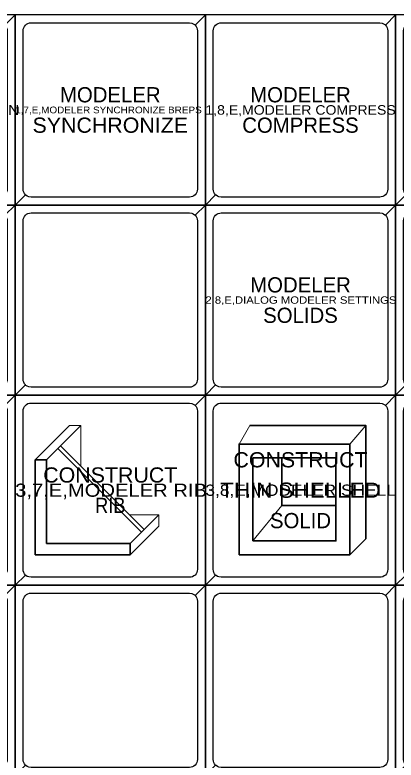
# Model space of a CAD drawing. Extents: x 95909.2 to 95923.3, y 90965 to 90971.2.
# Drawn here: x 95913.386 to 95914.588, y 90968.808 to 90971.16 of the extents above; entities that cross this region are included whole.
import ezdxf
from ezdxf.enums import TextEntityAlignment as Align

# ---------------------------------------------------------------- set-up
doc = ezdxf.new("R2010")
doc.units = 0
doc.header["$LTSCALE"] = 0.019
for name, color, linetype, lineweight in [('1', 7, 'Continuous', 25), ('10', 7, 'Continuous', 13), ('2', 7, 'Continuous', 25), ('3', 7, 'Continuous', 25), ('4', 7, 'Continuous', 25), ('6', 7, 'Continuous', 13)]:
    doc.layers.add(name, color=color, linetype=linetype, lineweight=lineweight)
for name, color, linetype in [('5', 7, 'Continuous'), ('63', 7, 'Continuous'), ('9', 7, 'Continuous')]:
    doc.layers.add(name, color=color, linetype=linetype)

msp = doc.modelspace()

# ---------------------------------------------------------------- linework, layer by layer
at = {"layer": '1'}
for points in [[(95912.7868, 90970.5603), (95913.3868, 90970.5603), (95913.3868, 90971.1603), (95912.7868, 90971.1603)], [(95913.3868, 90970.5603), (95913.9868, 90970.5603), (95913.9868, 90971.1603), (95913.3868, 90971.1603)], [(95913.9868, 90970.5603), (95914.5868, 90970.5603), (95914.5868, 90971.1603), (95913.9868, 90971.1603)], [(95914.5868, 90970.5603), (95915.1868, 90970.5603), (95915.1868, 90971.1603), (95914.5868, 90971.1603)], [(95912.7868, 90969.9603), (95913.3868, 90969.9603), (95913.3868, 90970.5603), (95912.7868, 90970.5603)], [(95913.3868, 90969.9603), (95913.9868, 90969.9603), (95913.9868, 90970.5603), (95913.3868, 90970.5603)], [(95913.9868, 90969.9603), (95914.5868, 90969.9603), (95914.5868, 90970.5603), (95913.9868, 90970.5603)], [(95914.5868, 90969.9603), (95915.1868, 90969.9603), (95915.1868, 90970.5603), (95914.5868, 90970.5603)], [(95912.7868, 90969.3603), (95913.3868, 90969.3603), (95913.3868, 90969.9603), (95912.7868, 90969.9603)], [(95913.3868, 90969.3603), (95913.9868, 90969.3603), (95913.9868, 90969.9603), (95913.3868, 90969.9603)], [(95913.9868, 90969.3603), (95914.5868, 90969.3603), (95914.5868, 90969.9603), (95913.9868, 90969.9603)], [(95914.5868, 90969.3603), (95915.1868, 90969.3603), (95915.1868, 90969.9603), (95914.5868, 90969.9603)], [(95912.7868, 90968.7603), (95913.3868, 90968.7603), (95913.3868, 90969.3603), (95912.7868, 90969.3603)], [(95913.3868, 90968.7603), (95913.9868, 90968.7603), (95913.9868, 90969.3603), (95913.3868, 90969.3603)], [(95913.9868, 90968.7603), (95914.5868, 90968.7603), (95914.5868, 90969.3603), (95913.9868, 90969.3603)], [(95914.5868, 90968.7603), (95915.1868, 90968.7603), (95915.1868, 90969.3603), (95914.5868, 90969.3603)]]:
    msp.add_lwpolyline(points, close=True, dxfattribs=at)
at = {"layer": '10'}
msp.add_lwpolyline([(95909.7868, 90971.1603), (95915.7868, 90971.1603), (95915.7868, 90966.3603), (95909.7868, 90966.3603)], close=True, dxfattribs=at)
at = {"layer": '2'}
for points in [[(95912.7868, 90970.5603), (95913.3868, 90970.5603), (95913.3868, 90971.1603), (95912.7868, 90971.1603)], [(95913.3868, 90970.5603), (95913.9868, 90970.5603), (95913.9868, 90971.1603), (95913.3868, 90971.1603)], [(95913.9868, 90970.5603), (95914.5868, 90970.5603), (95914.5868, 90971.1603), (95913.9868, 90971.1603)], [(95914.5868, 90970.5603), (95915.1868, 90970.5603), (95915.1868, 90971.1603), (95914.5868, 90971.1603)], [(95912.7868, 90969.9603), (95913.3868, 90969.9603), (95913.3868, 90970.5603), (95912.7868, 90970.5603)], [(95913.3868, 90969.9603), (95913.9868, 90969.9603), (95913.9868, 90970.5603), (95913.3868, 90970.5603)], [(95913.9868, 90969.9603), (95914.5868, 90969.9603), (95914.5868, 90970.5603), (95913.9868, 90970.5603)], [(95914.5868, 90969.9603), (95915.1868, 90969.9603), (95915.1868, 90970.5603), (95914.5868, 90970.5603)], [(95912.7868, 90969.3603), (95913.3868, 90969.3603), (95913.3868, 90969.9603), (95912.7868, 90969.9603)], [(95913.3868, 90969.3603), (95913.9868, 90969.3603), (95913.9868, 90969.9603), (95913.3868, 90969.9603)], [(95913.9868, 90969.3603), (95914.5868, 90969.3603), (95914.5868, 90969.9603), (95913.9868, 90969.9603)], [(95914.5868, 90969.3603), (95915.1868, 90969.3603), (95915.1868, 90969.9603), (95914.5868, 90969.9603)], [(95912.7868, 90968.7603), (95913.3868, 90968.7603), (95913.3868, 90969.3603), (95912.7868, 90969.3603)], [(95913.3868, 90968.7603), (95913.9868, 90968.7603), (95913.9868, 90969.3603), (95913.3868, 90969.3603)], [(95913.9868, 90968.7603), (95914.5868, 90968.7603), (95914.5868, 90969.3603), (95913.9868, 90969.3603)], [(95914.5868, 90968.7603), (95915.1868, 90968.7603), (95915.1868, 90969.3603), (95914.5868, 90969.3603)]]:
    msp.add_lwpolyline(points, close=True, dxfattribs=at)
at = {"layer": '3'}
for points in [[(95913.3868, 90971.1603), (95912.7868, 90971.1603), (95912.7868, 90970.5603), (95912.8191, 90970.5926), (95912.816, 90970.5964), (95912.8137, 90970.6007), (95912.8123, 90970.6054), (95912.8118, 90970.6103), (95912.8118, 90971.1103), (95912.8123, 90971.1152), (95912.8137, 90971.1199), (95912.816, 90971.1242), (95912.8191, 90971.128), (95912.8191, 90971.128), (95912.8229, 90971.1311), (95912.8272, 90971.1334), (95912.8319, 90971.1348), (95912.8368, 90971.1353), (95913.3368, 90971.1353), (95913.3441, 90971.1342), (95913.3486, 90971.1323), (95913.3527, 90971.1296), (95913.3545, 90971.128)], [(95913.9868, 90971.1603), (95913.3868, 90971.1603), (95913.3868, 90970.5603), (95913.4191, 90970.5926), (95913.416, 90970.5964), (95913.4137, 90970.6007), (95913.4123, 90970.6054), (95913.4118, 90970.6103), (95913.4118, 90971.1103), (95913.4123, 90971.1152), (95913.4137, 90971.1199), (95913.416, 90971.1242), (95913.4191, 90971.128), (95913.4191, 90971.128), (95913.4229, 90971.1311), (95913.4272, 90971.1334), (95913.4319, 90971.1348), (95913.4368, 90971.1353), (95913.9368, 90971.1353), (95913.9441, 90971.1342), (95913.9486, 90971.1323), (95913.9527, 90971.1296), (95913.9545, 90971.128)], [(95914.5868, 90971.1603), (95913.9868, 90971.1603), (95913.9868, 90970.5603), (95914.0191, 90970.5926), (95914.016, 90970.5964), (95914.0137, 90970.6007), (95914.0123, 90970.6054), (95914.0118, 90970.6103), (95914.0118, 90971.1103), (95914.0123, 90971.1152), (95914.0137, 90971.1199), (95914.016, 90971.1242), (95914.0191, 90971.128), (95914.0191, 90971.128), (95914.0229, 90971.1311), (95914.0272, 90971.1334), (95914.0319, 90971.1348), (95914.0368, 90971.1353), (95914.5368, 90971.1353), (95914.5441, 90971.1342), (95914.5486, 90971.1323), (95914.5527, 90971.1296), (95914.5545, 90971.128)], [(95915.1868, 90971.1603), (95914.5868, 90971.1603), (95914.5868, 90970.5603), (95914.6191, 90970.5926), (95914.616, 90970.5964), (95914.6137, 90970.6007), (95914.6123, 90970.6054), (95914.6118, 90970.6103), (95914.6118, 90971.1103), (95914.6123, 90971.1152), (95914.6137, 90971.1199), (95914.616, 90971.1242), (95914.6191, 90971.128), (95914.6191, 90971.128), (95914.6229, 90971.1311), (95914.6272, 90971.1334), (95914.6319, 90971.1348), (95914.6368, 90971.1353), (95915.1368, 90971.1353), (95915.1441, 90971.1342), (95915.1486, 90971.1323), (95915.1527, 90971.1296), (95915.1545, 90971.128)], [(95913.3868, 90970.5603), (95912.7868, 90970.5603), (95912.7868, 90969.9603), (95912.8191, 90969.9926), (95912.816, 90969.9964), (95912.8137, 90970.0007), (95912.8123, 90970.0054), (95912.8118, 90970.0103), (95912.8118, 90970.5103), (95912.8123, 90970.5152), (95912.8137, 90970.5199), (95912.816, 90970.5242), (95912.8191, 90970.528), (95912.8191, 90970.528), (95912.8229, 90970.5311), (95912.8272, 90970.5334), (95912.8319, 90970.5348), (95912.8368, 90970.5353), (95913.3368, 90970.5353), (95913.3441, 90970.5342), (95913.3486, 90970.5323), (95913.3527, 90970.5296), (95913.3545, 90970.528)], [(95913.9868, 90970.5603), (95913.3868, 90970.5603), (95913.3868, 90969.9603), (95913.4191, 90969.9926), (95913.416, 90969.9964), (95913.4137, 90970.0007), (95913.4123, 90970.0054), (95913.4118, 90970.0103), (95913.4118, 90970.5103), (95913.4123, 90970.5152), (95913.4137, 90970.5199), (95913.416, 90970.5242), (95913.4191, 90970.528), (95913.4191, 90970.528), (95913.4229, 90970.5311), (95913.4272, 90970.5334), (95913.4319, 90970.5348), (95913.4368, 90970.5353), (95913.9368, 90970.5353), (95913.9441, 90970.5342), (95913.9486, 90970.5323), (95913.9527, 90970.5296), (95913.9545, 90970.528)], [(95914.5868, 90970.5603), (95913.9868, 90970.5603), (95913.9868, 90969.9603), (95914.0191, 90969.9926), (95914.016, 90969.9964), (95914.0137, 90970.0007), (95914.0123, 90970.0054), (95914.0118, 90970.0103), (95914.0118, 90970.5103), (95914.0123, 90970.5152), (95914.0137, 90970.5199), (95914.016, 90970.5242), (95914.0191, 90970.528), (95914.0191, 90970.528), (95914.0229, 90970.5311), (95914.0272, 90970.5334), (95914.0319, 90970.5348), (95914.0368, 90970.5353), (95914.5368, 90970.5353), (95914.5441, 90970.5342), (95914.5486, 90970.5323), (95914.5527, 90970.5296), (95914.5545, 90970.528)], [(95915.1868, 90970.5603), (95914.5868, 90970.5603), (95914.5868, 90969.9603), (95914.6191, 90969.9926), (95914.616, 90969.9964), (95914.6137, 90970.0007), (95914.6123, 90970.0054), (95914.6118, 90970.0103), (95914.6118, 90970.5103), (95914.6123, 90970.5152), (95914.6137, 90970.5199), (95914.616, 90970.5242), (95914.6191, 90970.528), (95914.6191, 90970.528), (95914.6229, 90970.5311), (95914.6272, 90970.5334), (95914.6319, 90970.5348), (95914.6368, 90970.5353), (95915.1368, 90970.5353), (95915.1441, 90970.5342), (95915.1486, 90970.5323), (95915.1527, 90970.5296), (95915.1545, 90970.528)], [(95913.3868, 90969.9603), (95912.7868, 90969.9603), (95912.7868, 90969.3603), (95912.8191, 90969.3926), (95912.816, 90969.3964), (95912.8137, 90969.4007), (95912.8123, 90969.4054), (95912.8118, 90969.4103), (95912.8118, 90969.9103), (95912.8123, 90969.9152), (95912.8137, 90969.9199), (95912.816, 90969.9242), (95912.8191, 90969.928), (95912.8191, 90969.928), (95912.8229, 90969.9311), (95912.8272, 90969.9334), (95912.8319, 90969.9348), (95912.8368, 90969.9353), (95913.3368, 90969.9353), (95913.3441, 90969.9342), (95913.3486, 90969.9323), (95913.3527, 90969.9296), (95913.3545, 90969.928)], [(95913.9868, 90969.9603), (95913.3868, 90969.9603), (95913.3868, 90969.3603), (95913.4191, 90969.3926), (95913.416, 90969.3964), (95913.4137, 90969.4007), (95913.4123, 90969.4054), (95913.4118, 90969.4103), (95913.4118, 90969.9103), (95913.4123, 90969.9152), (95913.4137, 90969.9199), (95913.416, 90969.9242), (95913.4191, 90969.928), (95913.4191, 90969.928), (95913.4229, 90969.9311), (95913.4272, 90969.9334), (95913.4319, 90969.9348), (95913.4368, 90969.9353), (95913.9368, 90969.9353), (95913.9441, 90969.9342), (95913.9486, 90969.9323), (95913.9527, 90969.9296), (95913.9545, 90969.928)], [(95914.5868, 90969.9603), (95913.9868, 90969.9603), (95913.9868, 90969.3603), (95914.0191, 90969.3926), (95914.016, 90969.3964), (95914.0137, 90969.4007), (95914.0123, 90969.4054), (95914.0118, 90969.4103), (95914.0118, 90969.9103), (95914.0123, 90969.9152), (95914.0137, 90969.9199), (95914.016, 90969.9242), (95914.0191, 90969.928), (95914.0191, 90969.928), (95914.0229, 90969.9311), (95914.0272, 90969.9334), (95914.0319, 90969.9348), (95914.0368, 90969.9353), (95914.5368, 90969.9353), (95914.5441, 90969.9342), (95914.5486, 90969.9323), (95914.5527, 90969.9296), (95914.5545, 90969.928)], [(95915.1868, 90969.9603), (95914.5868, 90969.9603), (95914.5868, 90969.3603), (95914.6191, 90969.3926), (95914.616, 90969.3964), (95914.6137, 90969.4007), (95914.6123, 90969.4054), (95914.6118, 90969.4103), (95914.6118, 90969.9103), (95914.6123, 90969.9152), (95914.6137, 90969.9199), (95914.616, 90969.9242), (95914.6191, 90969.928), (95914.6191, 90969.928), (95914.6229, 90969.9311), (95914.6272, 90969.9334), (95914.6319, 90969.9348), (95914.6368, 90969.9353), (95915.1368, 90969.9353), (95915.1441, 90969.9342), (95915.1486, 90969.9323), (95915.1527, 90969.9296), (95915.1545, 90969.928)], [(95913.3868, 90969.3603), (95912.7868, 90969.3603), (95912.7868, 90968.7603), (95912.8191, 90968.7926), (95912.816, 90968.7964), (95912.8137, 90968.8007), (95912.8123, 90968.8054), (95912.8118, 90968.8103), (95912.8118, 90969.3103), (95912.8123, 90969.3152), (95912.8137, 90969.3199), (95912.816, 90969.3242), (95912.8191, 90969.328), (95912.8191, 90969.328), (95912.8229, 90969.3311), (95912.8272, 90969.3334), (95912.8319, 90969.3348), (95912.8368, 90969.3353), (95913.3368, 90969.3353), (95913.3441, 90969.3342), (95913.3486, 90969.3323), (95913.3527, 90969.3296), (95913.3545, 90969.328)], [(95913.9868, 90969.3603), (95913.3868, 90969.3603), (95913.3868, 90968.7603), (95913.4191, 90968.7926), (95913.416, 90968.7964), (95913.4137, 90968.8007), (95913.4123, 90968.8054), (95913.4118, 90968.8103), (95913.4118, 90969.3103), (95913.4123, 90969.3152), (95913.4137, 90969.3199), (95913.416, 90969.3242), (95913.4191, 90969.328), (95913.4191, 90969.328), (95913.4229, 90969.3311), (95913.4272, 90969.3334), (95913.4319, 90969.3348), (95913.4368, 90969.3353), (95913.9368, 90969.3353), (95913.9441, 90969.3342), (95913.9486, 90969.3323), (95913.9527, 90969.3296), (95913.9545, 90969.328)], [(95914.5868, 90969.3603), (95913.9868, 90969.3603), (95913.9868, 90968.7603), (95914.0191, 90968.7926), (95914.016, 90968.7964), (95914.0137, 90968.8007), (95914.0123, 90968.8054), (95914.0118, 90968.8103), (95914.0118, 90969.3103), (95914.0123, 90969.3152), (95914.0137, 90969.3199), (95914.016, 90969.3242), (95914.0191, 90969.328), (95914.0191, 90969.328), (95914.0229, 90969.3311), (95914.0272, 90969.3334), (95914.0319, 90969.3348), (95914.0368, 90969.3353), (95914.5368, 90969.3353), (95914.5441, 90969.3342), (95914.5486, 90969.3323), (95914.5527, 90969.3296), (95914.5545, 90969.328)], [(95915.1868, 90969.3603), (95914.5868, 90969.3603), (95914.5868, 90968.7603), (95914.6191, 90968.7926), (95914.616, 90968.7964), (95914.6137, 90968.8007), (95914.6123, 90968.8054), (95914.6118, 90968.8103), (95914.6118, 90969.3103), (95914.6123, 90969.3152), (95914.6137, 90969.3199), (95914.616, 90969.3242), (95914.6191, 90969.328), (95914.6191, 90969.328), (95914.6229, 90969.3311), (95914.6272, 90969.3334), (95914.6319, 90969.3348), (95914.6368, 90969.3353), (95915.1368, 90969.3353), (95915.1441, 90969.3342), (95915.1486, 90969.3323), (95915.1527, 90969.3296), (95915.1545, 90969.328)]]:
    msp.add_lwpolyline(points, close=True, dxfattribs=at)
at = {"layer": '4'}
for points in [[(95912.7868, 90970.5603), (95913.3868, 90970.5603), (95913.3868, 90971.1603), (95913.3545, 90971.128), (95913.3576, 90971.1242), (95913.3599, 90971.1199), (95913.3613, 90971.1152), (95913.3618, 90971.1103), (95913.3618, 90970.6103), (95913.3613, 90970.6054), (95913.3599, 90970.6007), (95913.3576, 90970.5964), (95913.3545, 90970.5926), (95913.3545, 90970.5926), (95913.3507, 90970.5895), (95913.3464, 90970.5872), (95913.3417, 90970.5858), (95913.3368, 90970.5853), (95912.8368, 90970.5853), (95912.8295, 90970.5864), (95912.825, 90970.5883), (95912.8209, 90970.591), (95912.8191, 90970.5926)], [(95913.3868, 90970.5603), (95913.9868, 90970.5603), (95913.9868, 90971.1603), (95913.9545, 90971.128), (95913.9576, 90971.1242), (95913.9599, 90971.1199), (95913.9613, 90971.1152), (95913.9618, 90971.1103), (95913.9618, 90970.6103), (95913.9613, 90970.6054), (95913.9599, 90970.6007), (95913.9576, 90970.5964), (95913.9545, 90970.5926), (95913.9545, 90970.5926), (95913.9507, 90970.5895), (95913.9464, 90970.5872), (95913.9417, 90970.5858), (95913.9368, 90970.5853), (95913.4368, 90970.5853), (95913.4295, 90970.5864), (95913.425, 90970.5883), (95913.4209, 90970.591), (95913.4191, 90970.5926)], [(95913.9868, 90970.5603), (95914.5868, 90970.5603), (95914.5868, 90971.1603), (95914.5545, 90971.128), (95914.5576, 90971.1242), (95914.5599, 90971.1199), (95914.5613, 90971.1152), (95914.5618, 90971.1103), (95914.5618, 90970.6103), (95914.5613, 90970.6054), (95914.5599, 90970.6007), (95914.5576, 90970.5964), (95914.5545, 90970.5926), (95914.5545, 90970.5926), (95914.5507, 90970.5895), (95914.5464, 90970.5872), (95914.5417, 90970.5858), (95914.5368, 90970.5853), (95914.0368, 90970.5853), (95914.0295, 90970.5864), (95914.025, 90970.5883), (95914.0209, 90970.591), (95914.0191, 90970.5926)], [(95914.5868, 90970.5603), (95915.1868, 90970.5603), (95915.1868, 90971.1603), (95915.1545, 90971.128), (95915.1576, 90971.1242), (95915.1599, 90971.1199), (95915.1613, 90971.1152), (95915.1618, 90971.1103), (95915.1618, 90970.6103), (95915.1613, 90970.6054), (95915.1599, 90970.6007), (95915.1576, 90970.5964), (95915.1545, 90970.5926), (95915.1545, 90970.5926), (95915.1507, 90970.5895), (95915.1464, 90970.5872), (95915.1417, 90970.5858), (95915.1368, 90970.5853), (95914.6368, 90970.5853), (95914.6295, 90970.5864), (95914.625, 90970.5883), (95914.6209, 90970.591), (95914.6191, 90970.5926)], [(95912.7868, 90969.9603), (95913.3868, 90969.9603), (95913.3868, 90970.5603), (95913.3545, 90970.528), (95913.3576, 90970.5242), (95913.3599, 90970.5199), (95913.3613, 90970.5152), (95913.3618, 90970.5103), (95913.3618, 90970.0103), (95913.3613, 90970.0054), (95913.3599, 90970.0007), (95913.3576, 90969.9964), (95913.3545, 90969.9926), (95913.3545, 90969.9926), (95913.3507, 90969.9895), (95913.3464, 90969.9872), (95913.3417, 90969.9858), (95913.3368, 90969.9853), (95912.8368, 90969.9853), (95912.8295, 90969.9864), (95912.825, 90969.9883), (95912.8209, 90969.991), (95912.8191, 90969.9926)], [(95913.3868, 90969.9603), (95913.9868, 90969.9603), (95913.9868, 90970.5603), (95913.9545, 90970.528), (95913.9576, 90970.5242), (95913.9599, 90970.5199), (95913.9613, 90970.5152), (95913.9618, 90970.5103), (95913.9618, 90970.0103), (95913.9613, 90970.0054), (95913.9599, 90970.0007), (95913.9576, 90969.9964), (95913.9545, 90969.9926), (95913.9545, 90969.9926), (95913.9507, 90969.9895), (95913.9464, 90969.9872), (95913.9417, 90969.9858), (95913.9368, 90969.9853), (95913.4368, 90969.9853), (95913.4295, 90969.9864), (95913.425, 90969.9883), (95913.4209, 90969.991), (95913.4191, 90969.9926)], [(95913.9868, 90969.9603), (95914.5868, 90969.9603), (95914.5868, 90970.5603), (95914.5545, 90970.528), (95914.5576, 90970.5242), (95914.5599, 90970.5199), (95914.5613, 90970.5152), (95914.5618, 90970.5103), (95914.5618, 90970.0103), (95914.5613, 90970.0054), (95914.5599, 90970.0007), (95914.5576, 90969.9964), (95914.5545, 90969.9926), (95914.5545, 90969.9926), (95914.5507, 90969.9895), (95914.5464, 90969.9872), (95914.5417, 90969.9858), (95914.5368, 90969.9853), (95914.0368, 90969.9853), (95914.0295, 90969.9864), (95914.025, 90969.9883), (95914.0209, 90969.991), (95914.0191, 90969.9926)], [(95914.5868, 90969.9603), (95915.1868, 90969.9603), (95915.1868, 90970.5603), (95915.1545, 90970.528), (95915.1576, 90970.5242), (95915.1599, 90970.5199), (95915.1613, 90970.5152), (95915.1618, 90970.5103), (95915.1618, 90970.0103), (95915.1613, 90970.0054), (95915.1599, 90970.0007), (95915.1576, 90969.9964), (95915.1545, 90969.9926), (95915.1545, 90969.9926), (95915.1507, 90969.9895), (95915.1464, 90969.9872), (95915.1417, 90969.9858), (95915.1368, 90969.9853), (95914.6368, 90969.9853), (95914.6295, 90969.9864), (95914.625, 90969.9883), (95914.6209, 90969.991), (95914.6191, 90969.9926)], [(95912.7868, 90969.3603), (95913.3868, 90969.3603), (95913.3868, 90969.9603), (95913.3545, 90969.928), (95913.3576, 90969.9242), (95913.3599, 90969.9199), (95913.3613, 90969.9152), (95913.3618, 90969.9103), (95913.3618, 90969.4103), (95913.3613, 90969.4054), (95913.3599, 90969.4007), (95913.3576, 90969.3964), (95913.3545, 90969.3926), (95913.3545, 90969.3926), (95913.3507, 90969.3895), (95913.3464, 90969.3872), (95913.3417, 90969.3858), (95913.3368, 90969.3853), (95912.8368, 90969.3853), (95912.8295, 90969.3864), (95912.825, 90969.3883), (95912.8209, 90969.391), (95912.8191, 90969.3926)], [(95913.3868, 90969.3603), (95913.9868, 90969.3603), (95913.9868, 90969.9603), (95913.9545, 90969.928), (95913.9576, 90969.9242), (95913.9599, 90969.9199), (95913.9613, 90969.9152), (95913.9618, 90969.9103), (95913.9618, 90969.4103), (95913.9613, 90969.4054), (95913.9599, 90969.4007), (95913.9576, 90969.3964), (95913.9545, 90969.3926), (95913.9545, 90969.3926), (95913.9507, 90969.3895), (95913.9464, 90969.3872), (95913.9417, 90969.3858), (95913.9368, 90969.3853), (95913.4368, 90969.3853), (95913.4295, 90969.3864), (95913.425, 90969.3883), (95913.4209, 90969.391), (95913.4191, 90969.3926)], [(95913.9868, 90969.3603), (95914.5868, 90969.3603), (95914.5868, 90969.9603), (95914.5545, 90969.928), (95914.5576, 90969.9242), (95914.5599, 90969.9199), (95914.5613, 90969.9152), (95914.5618, 90969.9103), (95914.5618, 90969.4103), (95914.5613, 90969.4054), (95914.5599, 90969.4007), (95914.5576, 90969.3964), (95914.5545, 90969.3926), (95914.5545, 90969.3926), (95914.5507, 90969.3895), (95914.5464, 90969.3872), (95914.5417, 90969.3858), (95914.5368, 90969.3853), (95914.0368, 90969.3853), (95914.0295, 90969.3864), (95914.025, 90969.3883), (95914.0209, 90969.391), (95914.0191, 90969.3926)], [(95914.5868, 90969.3603), (95915.1868, 90969.3603), (95915.1868, 90969.9603), (95915.1545, 90969.928), (95915.1576, 90969.9242), (95915.1599, 90969.9199), (95915.1613, 90969.9152), (95915.1618, 90969.9103), (95915.1618, 90969.4103), (95915.1613, 90969.4054), (95915.1599, 90969.4007), (95915.1576, 90969.3964), (95915.1545, 90969.3926), (95915.1545, 90969.3926), (95915.1507, 90969.3895), (95915.1464, 90969.3872), (95915.1417, 90969.3858), (95915.1368, 90969.3853), (95914.6368, 90969.3853), (95914.6295, 90969.3864), (95914.625, 90969.3883), (95914.6209, 90969.391), (95914.6191, 90969.3926)], [(95912.7868, 90968.7603), (95913.3868, 90968.7603), (95913.3868, 90969.3603), (95913.3545, 90969.328), (95913.3576, 90969.3242), (95913.3599, 90969.3199), (95913.3613, 90969.3152), (95913.3618, 90969.3103), (95913.3618, 90968.8103), (95913.3613, 90968.8054), (95913.3599, 90968.8007), (95913.3576, 90968.7964), (95913.3545, 90968.7926), (95913.3545, 90968.7926), (95913.3507, 90968.7895), (95913.3464, 90968.7872), (95913.3417, 90968.7858), (95913.3368, 90968.7853), (95912.8368, 90968.7853), (95912.8295, 90968.7864), (95912.825, 90968.7883), (95912.8209, 90968.791), (95912.8191, 90968.7926)], [(95913.3868, 90968.7603), (95913.9868, 90968.7603), (95913.9868, 90969.3603), (95913.9545, 90969.328), (95913.9576, 90969.3242), (95913.9599, 90969.3199), (95913.9613, 90969.3152), (95913.9618, 90969.3103), (95913.9618, 90968.8103), (95913.9613, 90968.8054), (95913.9599, 90968.8007), (95913.9576, 90968.7964), (95913.9545, 90968.7926), (95913.9545, 90968.7926), (95913.9507, 90968.7895), (95913.9464, 90968.7872), (95913.9417, 90968.7858), (95913.9368, 90968.7853), (95913.4368, 90968.7853), (95913.4295, 90968.7864), (95913.425, 90968.7883), (95913.4209, 90968.791), (95913.4191, 90968.7926)], [(95913.9868, 90968.7603), (95914.5868, 90968.7603), (95914.5868, 90969.3603), (95914.5545, 90969.328), (95914.5576, 90969.3242), (95914.5599, 90969.3199), (95914.5613, 90969.3152), (95914.5618, 90969.3103), (95914.5618, 90968.8103), (95914.5613, 90968.8054), (95914.5599, 90968.8007), (95914.5576, 90968.7964), (95914.5545, 90968.7926), (95914.5545, 90968.7926), (95914.5507, 90968.7895), (95914.5464, 90968.7872), (95914.5417, 90968.7858), (95914.5368, 90968.7853), (95914.0368, 90968.7853), (95914.0295, 90968.7864), (95914.025, 90968.7883), (95914.0209, 90968.791), (95914.0191, 90968.7926)]]:
    msp.add_lwpolyline(points, close=True, dxfattribs=at)
at = {"layer": '6'}
for p, q in [((95913.4497, 90969.7563), (95913.5577, 90969.8643)), ((95913.4857, 90969.7563), (95913.5937, 90969.8643)), ((95913.5577, 90969.8643), (95913.5937, 90969.8643)), ((95913.5937, 90969.8643), (95913.5937, 90969.7372)), ((95914.0929, 90969.8057), (95914.1266, 90969.8643)), ((95914.4423, 90969.8057), (95914.4933, 90969.8643)), ((95914.1366, 90969.5), (95914.2275, 90969.6118)), ((95913.8397, 90969.5823), (95913.7487, 90969.5823)), ((95913.7497, 90969.4923), (95913.8397, 90969.5823)), ((95913.8397, 90969.5463), (95913.8397, 90969.5823)), ((95913.7497, 90969.4563), (95913.8397, 90969.5463)), ((95914.4423, 90969.4563), (95914.4933, 90969.5072))]:
    msp.add_line(p, q, dxfattribs=at)
at = {"layer": '6', "lineweight": 35}
for p, q in [((95913.5302, 90969.8007), (95913.7942, 90969.5367)), ((95913.5217, 90969.7923), (95913.7857, 90969.5283)), ((95913.4857, 90969.7563), (95913.4497, 90969.7563)), ((95913.4497, 90969.4563), (95913.4497, 90969.7563)), ((95914.2275, 90969.7621), (95914.2275, 90969.6118)), ((95914.3987, 90969.6118), (95914.2275, 90969.6118)), ((95913.7497, 90969.4563), (95913.7497, 90969.4923)), ((95913.4497, 90969.4563), (95913.7497, 90969.4563))]:
    msp.add_line(p, q, dxfattribs=at)
for points in [[(95914.4933, 90969.5072), (95914.4933, 90969.8643), (95914.1266, 90969.8643)], [(95913.4857, 90969.7563), (95913.4857, 90969.4923), (95913.7497, 90969.4923)]]:
    msp.add_lwpolyline(points, dxfattribs=at)
for points in [[(95914.0929, 90969.4563), (95914.4423, 90969.4563), (95914.4423, 90969.8057), (95914.0929, 90969.8057)], [(95914.1366, 90969.5), (95914.3987, 90969.5), (95914.3987, 90969.7621), (95914.1366, 90969.7621)]]:
    msp.add_lwpolyline(points, close=True, dxfattribs=at)

# ---------------------------------------------------------------- texts
at = {"layer": '5'}
for s, width, p in [('CONSTRUCT', 1.05, (95914.2868, 90969.7323)), ('CONSTRUCT', 1.05, (95913.6868, 90969.6843)), ('THIN SHELLED', 1.1, (95914.28675, 90969.6363)), ('RIB', 0.9, (95913.6868, 90969.5883))]:
    msp.add_text(s, height=0.048, dxfattribs=dict(at, width=width)).set_placement(p, align=Align.CENTER)
msp.add_text('SOLID', height=0.048, dxfattribs=at).set_placement((95914.2868, 90969.5403), align=Align.CENTER)
at = {"layer": '63'}
for s, height, width, p in [('1,6,E,PLACE WEDGE ICON', 0.0313, 1.15, (95912.7868, 90970.8447)), ('1,8,E,MODELER COMPRESS', 0.0301, 1.1, (95913.9868, 90970.8453)), ('1,7,E,MODELER SYNCHRONIZE BREPS', 0.0213, 1.1, (95913.3868, 90970.8497)), ('2,8,E,DIALOG MODELER SETTINGS', 0.0232, 1.15, (95913.9868, 90970.2487)), ('3,7,E,MODELER RIB', 0.0414, 1.15, (95913.3868, 90969.6396)), ('3,8,E,MODELER SHELL', 0.0355, 1.15, (95913.9868, 90969.6425))]:
    msp.add_text(s, height=height, dxfattribs=dict(at, width=width)).set_placement(p)
at = {"layer": '9'}
for s, p in [('MODELER', (95913.68685, 90970.8843)), ('MODELER', (95914.28685, 90970.8843)), ('COMPRESS', (95914.2868, 90970.7883)), ('MODELER', (95914.28685, 90970.2843)), ('SOLIDS', (95914.2868, 90970.1883))]:
    msp.add_text(s, height=0.048, dxfattribs=at).set_placement(p, align=Align.CENTER)
at = {"layer": '9', "width": 1.05}
msp.add_text('SYNCHRONIZE', height=0.048, dxfattribs=at).set_placement((95913.6868, 90970.7883), align=Align.CENTER)

doc.saveas('drawing.dxf')
